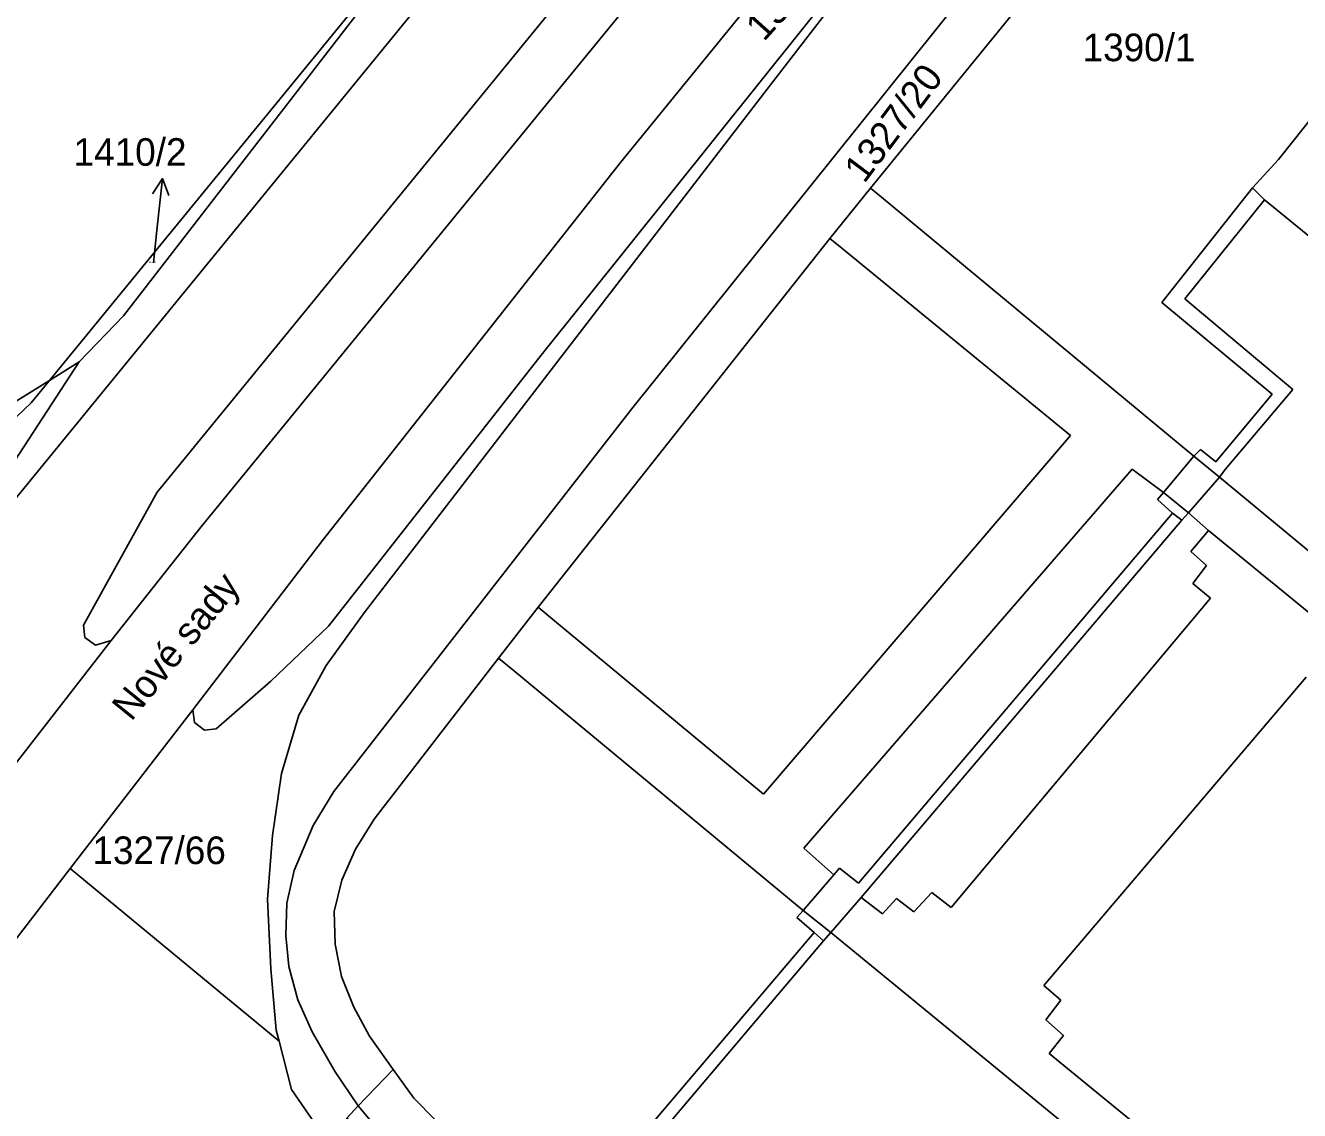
# Model space of a CAD drawing. Extents: x -598934 to -598196, y -1162208 to -1161502.
# Drawn here: x -598686.2 to -598607.7, y -1161897.6 to -1161830.8 of the extents above; entities that cross this region are included whole.
import ezdxf

# ---------------------------------------------------------------- set-up
doc = ezdxf.new("R2010")
doc.units = 0
for name, color, linetype in [('KN_CAR_KR', 7, 'Continuous'), ('KN_PARC_CIS_POM', 7, 'Continuous'), ('KN_PARC_CIS_POZ', 7, 'Continuous'), ('KN_PARC_PLOCHA', 7, 'Continuous'), ('KN_ULICE', 7, 'Continuous'), ('PARC_C_SIPKA', 7, 'Continuous'), ('parcely_l', 7, 'Continuous')]:
    doc.layers.add(name, color=color, linetype=linetype)

msp = doc.modelspace()

# ---------------------------------------------------------------- linework, layer by layer
at = {"layer": 'KN_CAR_KR'}
for points in [[(-598633.47, -1161841.37), (-598634.15, -1161840.81)], [(-598616.2, -1161847.85), (-598610.62, -1161840.79)], [(-598614.24, -1161857.32), (-598633.47, -1161841.37)], [(-598609.88, -1161841.52), (-598614.79, -1161847.63)], [(-598636.65, -1161843.9), (-598635.91, -1161844.5)], [(-598635.91, -1161844.5), (-598621.84, -1161856.03)], [(-598609.42, -1161853.5), (-598616.2, -1161847.85)], [(-598614.79, -1161847.63), (-598608.14, -1161853.2)], [(-598612.88, -1161857.67), (-598609.42, -1161853.5)], [(-598608.14, -1161853.2), (-598612.3, -1161858.13)], [(-598621.84, -1161856.03), (-598640.74, -1161878.12)], [(-598616.1, -1161859.55), (-598614.24, -1161857.32)], [(-598614.24, -1161857.32), (-598613.82, -1161856.91)], [(-598614.24, -1161857.32), (-598612.66, -1161858.6)], [(-598613.82, -1161856.91), (-598612.88, -1161857.67)], [(-598638.25, -1161881.46), (-598618.04, -1161858.12)], [(-598618.04, -1161858.12), (-598616.1, -1161859.55)], [(-598612.3, -1161858.13), (-598612.66, -1161858.6)], [(-598612.66, -1161858.6), (-598614.56, -1161860.81)], [(-598612.66, -1161858.6), (-598606.83, -1161863.43)], [(-598616.1, -1161859.55), (-598616.48, -1161859.98)], [(-598616.48, -1161859.98), (-598615.55, -1161860.82)], [(-598616.1, -1161859.55), (-598614.56, -1161860.81)], [(-598615.55, -1161860.82), (-598634.89, -1161883.61)], [(-598614.97, -1161861.25), (-598634.73, -1161884.48)], [(-598615.55, -1161860.82), (-598614.97, -1161861.25)], [(-598614.56, -1161860.81), (-598614.97, -1161861.25)], [(-598614.56, -1161860.81), (-598613.34, -1161861.88)], [(-598613.34, -1161861.88), (-598614.43, -1161863.19)], [(-598613.34, -1161861.88), (-598602.99, -1161870.34)], [(-598614.43, -1161863.19), (-598613.45, -1161864.04)], [(-598613.45, -1161864.04), (-598614.29, -1161865.15)], [(-598614.29, -1161865.15), (-598613.21, -1161866.06)], [(-598613.21, -1161866.06), (-598629.19, -1161885.11)], [(-598653.74, -1161867.34), (-598654.62, -1161866.6)], [(-598640.74, -1161878.12), (-598653.74, -1161867.34)], [(-598656.18, -1161870.47), (-598657.06, -1161869.74)], [(-598638.29, -1161885.29), (-598656.18, -1161870.47)], [(-598607.32, -1161870.91), (-598623.48, -1161889.91)], [(-598636.4, -1161883.1), (-598638.25, -1161881.46)], [(-598636.06, -1161882.69), (-598636.4, -1161883.1)], [(-598634.89, -1161883.61), (-598636.06, -1161882.69)], [(-598638.29, -1161885.29), (-598636.4, -1161883.1)], [(-598630.38, -1161884.17), (-598631.49, -1161885.37)], [(-598629.19, -1161885.11), (-598630.38, -1161884.17)], [(-598634.73, -1161884.48), (-598636.59, -1161886.64)], [(-598633.42, -1161885.5), (-598634.73, -1161884.48)], [(-598632.54, -1161884.54), (-598633.42, -1161885.5)], [(-598631.49, -1161885.37), (-598632.54, -1161884.54)], [(-598638.68, -1161885.71), (-598638.29, -1161885.29)], [(-598637.61, -1161886.65), (-598638.68, -1161885.71)], [(-598636.59, -1161886.64), (-598638.29, -1161885.29)], [(-598652.25, -1161903.88), (-598637.61, -1161886.65)], [(-598637.04, -1161887.15), (-598637.61, -1161886.65)], [(-598623.48, -1161889.91), (-598622.43, -1161890.82)], [(-598622.43, -1161890.82), (-598623.35, -1161892.03)], [(-598623.35, -1161892.03), (-598622.26, -1161892.99)], [(-598622.26, -1161892.99), (-598623.15, -1161894.09)], [(-598623.15, -1161894.09), (-598537.06, -1161964.54)], [(-598663.55, -1161895.07), (-598662.28, -1161896.84)], [(-598662.28, -1161896.84), (-598657.06, -1161902.15)]]:
    msp.add_lwpolyline(points, dxfattribs=at)
at = {"layer": 'KN_PARC_PLOCHA'}
for points in [[(-598569.06, -1161732.86), (-598601.28, -1161767.71), (-598618.28, -1161786.85), (-598631.03, -1161802.04), (-598653.94, -1161830.02), (-598678.08, -1161859.52), (-598682.61, -1161867.71), (-598682.53, -1161868.47), (-598681.88, -1161868.94), (-598680.91, -1161868.67), (-598688.55, -1161878.47)], [(-598688.55, -1161878.47), (-598680.91, -1161868.67), (-598675.39, -1161861.69), (-598653.59, -1161835.03), (-598631.91, -1161808.54), (-598615.63, -1161789.16), (-598615.93, -1161788.89), (-598599.26, -1161769.56), (-598580.79, -1161748.69)], [(-598575.91, -1161752.96), (-598593.14, -1161772.4), (-598610.98, -1161793.12), (-598611.27, -1161792.88), (-598628.18, -1161812.99), (-598649.55, -1161839.23), (-598667.89, -1161862.51), (-598675.89, -1161872.94), (-598683.43, -1161882.7), (-598688.82, -1161889.68)], [(-598686.85, -1161859.98), (-598651.94, -1161817.27), (-598623.21, -1161782.58), (-598621.23, -1161780.29), (-598620.02, -1161778.68), (-598619.07, -1161776.88), (-598617.95, -1161774.07), (-598617.1, -1161771.17), (-598616.77, -1161768.59), (-598617.01, -1161766.57), (-598617.64, -1161764.65), (-598618.77, -1161762.99), (-598621.01, -1161760.25), (-598615.08, -1161754.64)], [(-598630.21, -1161755.2), (-598623.69, -1161762.79), (-598622.33, -1161764.37), (-598621.1, -1161766.12), (-598620.74, -1161767.18), (-598620.65, -1161768.26), (-598620.99, -1161769.77), (-598621.75, -1161771.04), (-598626.97, -1161779.46), (-598638.82, -1161795.01), (-598658.47, -1161820.58), (-598684.71, -1161852.65), (-598686.76, -1161853.93)], [(-598687.99, -1161859.32), (-598682.88, -1161851.51), (-598680.15, -1161848.67), (-598661.99, -1161825.16), (-598658.47, -1161820.58), (-598640.57, -1161798.7), (-598626.97, -1161779.46), (-598619.12, -1161768.35), (-598621.1, -1161766.12), (-598622.33, -1161764.37), (-598623.69, -1161762.79), (-598621.01, -1161760.25), (-598618.77, -1161762.99), (-598617.64, -1161764.65), (-598617.01, -1161766.57), (-598616.77, -1161768.59), (-598617.1, -1161771.17), (-598617.95, -1161774.07), (-598619.07, -1161776.88), (-598620.02, -1161778.68), (-598621.23, -1161780.29), (-598623.21, -1161782.58), (-598651.94, -1161817.27), (-598686.85, -1161859.98)], [(-598667.72, -1161899.35), (-598669.8, -1161896.31), (-598670.57, -1161893.33), (-598670.75, -1161892.65), (-598671.09, -1161888.88), (-598671.28, -1161884.6), (-598670.98, -1161880.68), (-598670.43, -1161876.86), (-598669.36, -1161873.26), (-598667.67, -1161870.2), (-598665.33, -1161866.96), (-598640.52, -1161834.72), (-598626.62, -1161816.69)], [(-598618.02, -1161821.01), (-598634.15, -1161840.81), (-598636.65, -1161843.9), (-598654.62, -1161866.6), (-598657.06, -1161869.74), (-598664.72, -1161879.66), (-598665.86, -1161881.52), (-598666.7, -1161883.43), (-598667.17, -1161885.35), (-598667.12, -1161887.37), (-598666.73, -1161889.36), (-598665.97, -1161891.24), (-598665.01, -1161893.03), (-598663.55, -1161895.07), (-598665.71, -1161897.32), (-598667.11, -1161895.22), (-598668.53, -1161892.76), (-598669.42, -1161890.78), (-598669.97, -1161888.74), (-598670.16, -1161886.83), (-598670.1, -1161884.83), (-598669.64, -1161882.82), (-598668.47, -1161880.06), (-598667.2, -1161877.97), (-598648.87, -1161854.42), (-598628.49, -1161828.99)], [(-598664.45, -1161898.81), (-598665.71, -1161897.32), (-598663.55, -1161895.07), (-598665.01, -1161893.03), (-598665.97, -1161891.24), (-598666.73, -1161889.36), (-598667.12, -1161887.37), (-598667.17, -1161885.35), (-598666.7, -1161883.43), (-598665.86, -1161881.52), (-598664.72, -1161879.66), (-598657.06, -1161869.74), (-598654.62, -1161866.6), (-598636.65, -1161843.9), (-598634.15, -1161840.81), (-598618.02, -1161821.01)], [(-598628.49, -1161828.99), (-598648.87, -1161854.42), (-598667.2, -1161877.97), (-598668.47, -1161880.06), (-598669.64, -1161882.82), (-598670.1, -1161884.83), (-598670.16, -1161886.83), (-598669.97, -1161888.74), (-598669.42, -1161890.78), (-598668.53, -1161892.76), (-598667.11, -1161895.22), (-598665.71, -1161897.32), (-598666.41, -1161898.08)], [(-598555.37, -1161871.55), (-598560.71, -1161867.12), (-598566.15, -1161862.69), (-598566.54, -1161862.3), (-598568.81, -1161860.43), (-598574.98, -1161855.42), (-598581.1, -1161850.37), (-598583.05, -1161848.77), (-598589.24, -1161843.66), (-598595.26, -1161838.7), (-598597.15, -1161837.12), (-598603.04, -1161832.31), (-598603.43, -1161832.01), (-598609.03, -1161839.04), (-598610.62, -1161840.79), (-598609.88, -1161841.52), (-598596.51, -1161852.44), (-598590.23, -1161857.7), (-598588.04, -1161859.4), (-598582.16, -1161864.26), (-598567.98, -1161875.86), (-598561.82, -1161880.97), (-598559.56, -1161882.84), (-598553.72, -1161887.6)]]:
    msp.add_lwpolyline(points, dxfattribs=at)
for points in [[(-598615.93, -1161788.89), (-598615.63, -1161789.16), (-598631.91, -1161808.54), (-598653.59, -1161835.03), (-598675.39, -1161861.69), (-598680.91, -1161868.67), (-598681.88, -1161868.94), (-598682.53, -1161868.47), (-598682.61, -1161867.71), (-598678.08, -1161859.52), (-598653.94, -1161830.02), (-598631.03, -1161802.04), (-598618.28, -1161786.85)], [(-598610.98, -1161793.12), (-598608.6, -1161795.18), (-598611.28, -1161798.37), (-598612.86, -1161799.4), (-598615.32, -1161802.03), (-598626.62, -1161816.69), (-598633.01, -1161824.32), (-598654.44, -1161851.1), (-598667.53, -1161867.77), (-598671.08, -1161871.16), (-598674.45, -1161874.1), (-598675.17, -1161874.19), (-598675.79, -1161873.71), (-598675.89, -1161872.94), (-598667.89, -1161862.51), (-598649.55, -1161839.23), (-598628.18, -1161812.99), (-598611.27, -1161792.88)], [(-598670.57, -1161893.33), (-598683.43, -1161882.7), (-598675.89, -1161872.94), (-598675.79, -1161873.71), (-598675.17, -1161874.19), (-598674.45, -1161874.1), (-598671.08, -1161871.16), (-598667.53, -1161867.77), (-598654.44, -1161851.1), (-598633.01, -1161824.32), (-598626.62, -1161816.69), (-598640.52, -1161834.72), (-598665.33, -1161866.96), (-598667.67, -1161870.2), (-598669.36, -1161873.26), (-598670.43, -1161876.86), (-598670.98, -1161880.68), (-598671.28, -1161884.6), (-598671.09, -1161888.88), (-598670.75, -1161892.65)], [(-598682.88, -1161851.51), (-598684.71, -1161852.65), (-598658.47, -1161820.58), (-598661.99, -1161825.16), (-598680.15, -1161848.67)], [(-598589.24, -1161843.66), (-598596.51, -1161852.44), (-598609.88, -1161841.52), (-598610.62, -1161840.79), (-598609.03, -1161839.04), (-598603.43, -1161832.01), (-598603.04, -1161832.31), (-598597.15, -1161837.12), (-598595.26, -1161838.7)], [(-598687.99, -1161859.32), (-598695.67, -1161861.22), (-598697.55, -1161862.07), (-598697.71, -1161862.22), (-598697.96, -1161862.18), (-598703.41, -1161860.33), (-598699.95, -1161856.31), (-598699.01, -1161856.64), (-598697.05, -1161857.17), (-598695.03, -1161857.44), (-598693.03, -1161857.46), (-598691.02, -1161857.11), (-598689.09, -1161856.45), (-598687.2, -1161855.32), (-598685.83, -1161854.02), (-598684.71, -1161852.65), (-598682.88, -1161851.51)], [(-598699.95, -1161856.31), (-598699.75, -1161856.08), (-598697.48, -1161856.32), (-598690.74, -1161855.18), (-598686.76, -1161853.93), (-598684.71, -1161852.65), (-598685.83, -1161854.02), (-598687.2, -1161855.32), (-598689.09, -1161856.45), (-598691.02, -1161857.11), (-598693.03, -1161857.46), (-598695.03, -1161857.44), (-598697.05, -1161857.17), (-598699.01, -1161856.64)], [(-598670.57, -1161893.33), (-598669.8, -1161896.31), (-598667.72, -1161899.35), (-598669.24, -1161900.87), (-598672.85, -1161904.41), (-598677.88, -1161909.36), (-598680.13, -1161909.46), (-598682.02, -1161909.99), (-598683.3, -1161910.59), (-598684, -1161911.17), (-598695.16, -1161897.89), (-598688.82, -1161889.68), (-598683.43, -1161882.7)], [(-598538.52, -1161967.05), (-598636.59, -1161886.64), (-598637.04, -1161887.15), (-598651.19, -1161903.86), (-598625.52, -1161927.53), (-598619.21, -1161933), (-598613.47, -1161937.67), (-598608.15, -1161941.8), (-598600.71, -1161947.3), (-598593.56, -1161952.32), (-598584.52, -1161958.15), (-598575.16, -1161963.39), (-598561.46, -1161970.35), (-598547.04, -1161976.92)], [(-598538.52, -1161967.05), (-598547.04, -1161976.92), (-598561.46, -1161970.35), (-598575.16, -1161963.39), (-598584.52, -1161958.15), (-598593.56, -1161952.32), (-598600.71, -1161947.3), (-598608.15, -1161941.8), (-598613.47, -1161937.67), (-598619.21, -1161933), (-598625.52, -1161927.53), (-598651.19, -1161903.86), (-598637.04, -1161887.15), (-598636.59, -1161886.64)], [(-598659.32, -1161904.21), (-598666.41, -1161898.08), (-598665.71, -1161897.32), (-598664.45, -1161898.81)]]:
    msp.add_lwpolyline(points, close=True, dxfattribs=at)
at = {"layer": 'PARC_C_SIPKA'}
for points in [[(-598678.364, -1161841.158), (-598677.761, -1161840.217), (-598677.37, -1161841.265)], [(-598678.31, -1161845.41), (-598678.08, -1161843.2), (-598677.761, -1161840.217)]]:
    msp.add_lwpolyline(points, dxfattribs=at)
at = {"layer": 'parcely_l'}
for points in [[(-598686.85, -1161859.98), (-598651.94, -1161817.27), (-598623.21, -1161782.58), (-598621.23, -1161780.29), (-598620.02, -1161778.68), (-598619.07, -1161776.88), (-598617.95, -1161774.07), (-598617.1, -1161771.17), (-598616.77, -1161768.59), (-598617.01, -1161766.57), (-598617.64, -1161764.65), (-598618.77, -1161762.99), (-598621.01, -1161760.25)], [(-598680.91, -1161868.67), (-598681.88, -1161868.94), (-598682.53, -1161868.47), (-598682.61, -1161867.71), (-598678.08, -1161859.52), (-598653.94, -1161830.02), (-598631.03, -1161802.04), (-598618.28, -1161786.85)], [(-598680.91, -1161868.67), (-598675.39, -1161861.69), (-598653.59, -1161835.03), (-598631.91, -1161808.54), (-598615.63, -1161789.16), (-598615.93, -1161788.89)], [(-598610.98, -1161793.12), (-598611.27, -1161792.88), (-598628.18, -1161812.99), (-598649.55, -1161839.23), (-598667.89, -1161862.51), (-598675.89, -1161872.94)], [(-598596.16, -1161800.8), (-598597.29, -1161800.15), (-598599.15, -1161799.59), (-598601.23, -1161799.55), (-598603.2, -1161800.09), (-598604.98, -1161801.19), (-598607.04, -1161803.34), (-598628.49, -1161828.99), (-598648.87, -1161854.42), (-598667.2, -1161877.97), (-598668.47, -1161880.06), (-598669.64, -1161882.82), (-598670.1, -1161884.83), (-598670.16, -1161886.83), (-598669.97, -1161888.74), (-598669.42, -1161890.78), (-598668.53, -1161892.76), (-598667.11, -1161895.22), (-598665.71, -1161897.32)], [(-598665.71, -1161897.32), (-598663.55, -1161895.07), (-598665.01, -1161893.03), (-598665.97, -1161891.24), (-598666.73, -1161889.36), (-598667.12, -1161887.37), (-598667.17, -1161885.35), (-598666.7, -1161883.43), (-598665.86, -1161881.52), (-598664.72, -1161879.66), (-598657.06, -1161869.74), (-598654.62, -1161866.6), (-598636.65, -1161843.9), (-598634.15, -1161840.81), (-598618.02, -1161821.01), (-598609.3, -1161810.66), (-598607.47, -1161808.89), (-598605.55, -1161808.08), (-598603.61, -1161807.81), (-598602.11, -1161808.08), (-598600.26, -1161805.7), (-598597.21, -1161802.09)], [(-598675.89, -1161872.94), (-598675.79, -1161873.71), (-598675.17, -1161874.19), (-598674.45, -1161874.1), (-598671.08, -1161871.16), (-598667.53, -1161867.77), (-598654.44, -1161851.1), (-598633.01, -1161824.32), (-598626.62, -1161816.69)], [(-598626.62, -1161816.69), (-598640.52, -1161834.72), (-598665.33, -1161866.96), (-598667.67, -1161870.2), (-598669.36, -1161873.26), (-598670.43, -1161876.86), (-598670.98, -1161880.68), (-598671.28, -1161884.6), (-598671.09, -1161888.88), (-598670.75, -1161892.65), (-598670.57, -1161893.33)], [(-598658.47, -1161820.58), (-598684.71, -1161852.65)], [(-598658.47, -1161820.58), (-598661.99, -1161825.16), (-598680.15, -1161848.67), (-598682.88, -1161851.51)], [(-598589.24, -1161843.66), (-598595.26, -1161838.7), (-598597.15, -1161837.12), (-598603.04, -1161832.31), (-598603.43, -1161832.01), (-598609.03, -1161839.04), (-598610.62, -1161840.79), (-598609.88, -1161841.52), (-598596.51, -1161852.44)], [(-598682.88, -1161851.51), (-598687.99, -1161859.32)], [(-598684.71, -1161852.65), (-598682.88, -1161851.51)], [(-598699.95, -1161856.31), (-598699.01, -1161856.64), (-598697.05, -1161857.17), (-598695.03, -1161857.44), (-598693.03, -1161857.46), (-598691.02, -1161857.11), (-598689.09, -1161856.45), (-598687.2, -1161855.32), (-598685.83, -1161854.02), (-598684.71, -1161852.65)], [(-598699.75, -1161856.08), (-598697.48, -1161856.32), (-598690.74, -1161855.18), (-598686.76, -1161853.93), (-598684.71, -1161852.65)], [(-598688.55, -1161878.47), (-598680.91, -1161868.67)], [(-598683.43, -1161882.7), (-598675.89, -1161872.94)], [(-598695.16, -1161897.89), (-598688.82, -1161889.68), (-598683.43, -1161882.7)], [(-598670.57, -1161893.33), (-598683.43, -1161882.7)], [(-598538.52, -1161967.05), (-598547.04, -1161976.92), (-598561.46, -1161970.35), (-598575.16, -1161963.39), (-598584.52, -1161958.15), (-598593.56, -1161952.32), (-598600.71, -1161947.3), (-598608.15, -1161941.8), (-598613.47, -1161937.67), (-598619.21, -1161933), (-598625.52, -1161927.53), (-598651.19, -1161903.86), (-598637.04, -1161887.15), (-598636.59, -1161886.64), (-598538.52, -1161967.05)], [(-598670.57, -1161893.33), (-598669.8, -1161896.31), (-598667.72, -1161899.35)], [(-598665.71, -1161897.32), (-598666.41, -1161898.08)], [(-598665.71, -1161897.32), (-598664.45, -1161898.81), (-598659.32, -1161904.21)]]:
    msp.add_lwpolyline(points, dxfattribs=at)

# ---------------------------------------------------------------- texts
at = {"layer": 'KN_PARC_CIS_POM'}
msp.add_text('1410/2', height=0.1, dxfattribs=at).set_placement((-598678.593, -1161845.41))
at = {"layer": 'KN_PARC_CIS_POZ'}
for s, rotation, p in [('1327/61', 48.04514, (-598640.718, -1161831.834)), ('1327/20', 53.09987, (-598634.536, -1161840.572))]:
    msp.add_text(s, height=1.7, rotation=rotation, dxfattribs=at).set_placement(p)
for s, p in [('1390/1', (-598621.087, -1161832.99)), ('1410/2', (-598683.227, -1161839.43)), ('1327/66', (-598682.067, -1161882.43))]:
    msp.add_text(s, height=1.7, dxfattribs=at).set_placement(p)
at = {"layer": 'KN_ULICE'}
msp.add_text('Nové sady', height=1.7, rotation=50.91442, dxfattribs=at).set_placement((-598679.675, -1161873.694))

doc.saveas('drawing.dxf')
